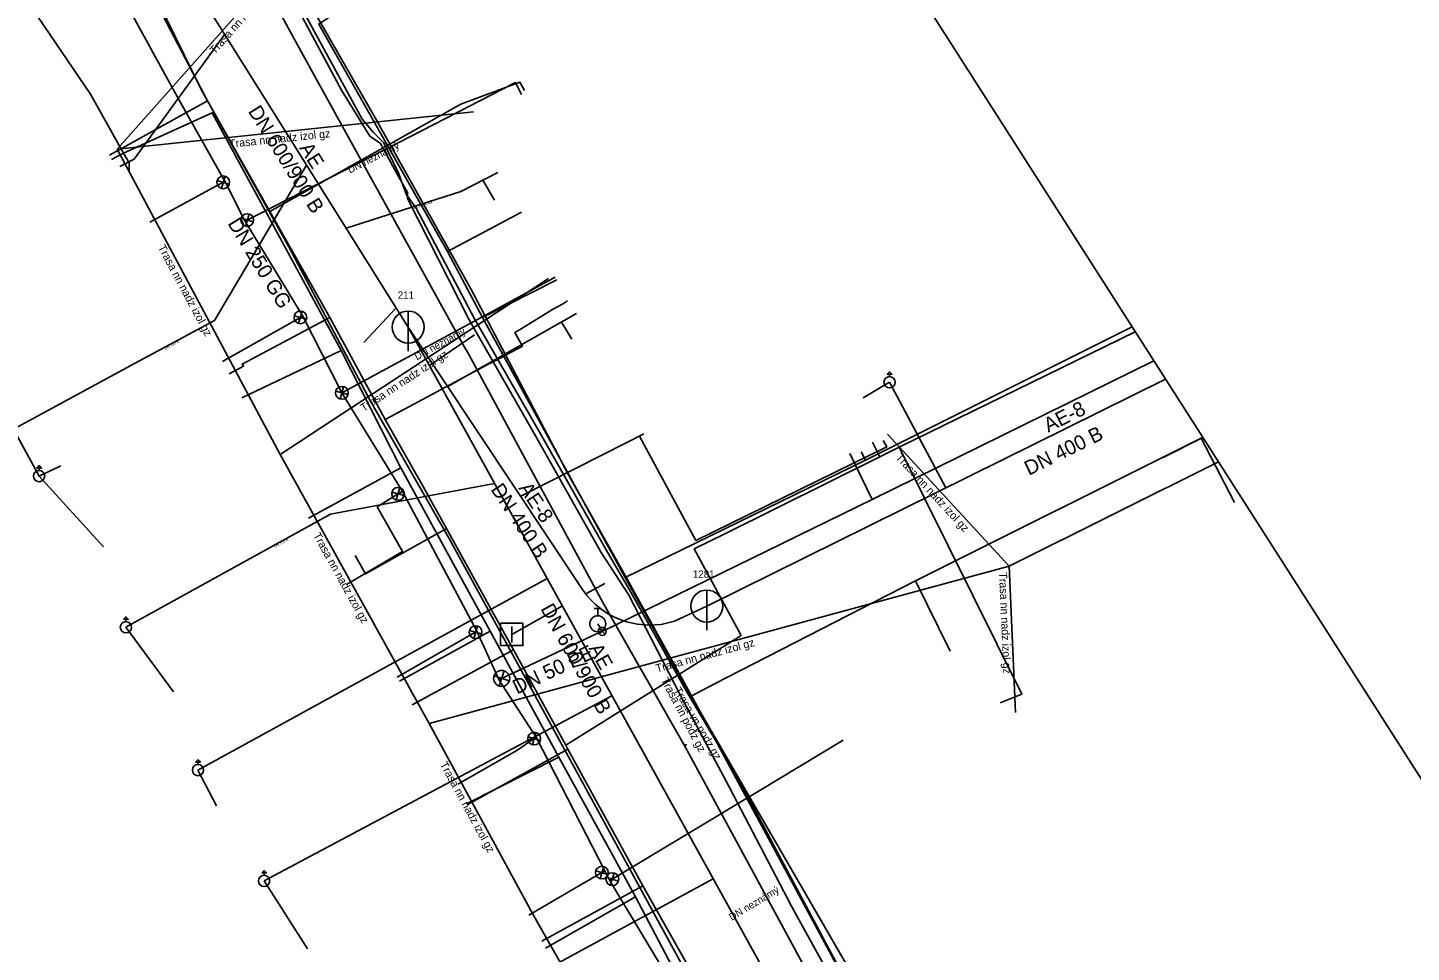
# Model space of a CAD drawing. Extents: x -493753 to -49291, y -1127285 to -112662.
# Drawn here: x -492942.9 to -492856.4, y -1126694.5 to -1126636.7 of the extents above; entities that cross this region are included whole.
import ezdxf

# ---------------------------------------------------------------- set-up
doc = ezdxf.new("R2010")
doc.units = 0
for name, color, linetype in [('Vrstva 1', 7, 'Continuous'), ('Vrstva 11', 7, 'Continuous'), ('Vrstva 15', 7, 'Continuous'), ('Vrstva 17', 7, 'Continuous'), ('Vrstva 19', 7, 'Continuous'), ('Vrstva 20', 7, 'Continuous'), ('Vrstva 22', 7, 'Continuous'), ('Vrstva 24', 7, 'Continuous'), ('Vrstva 26', 7, 'Continuous'), ('Vrstva 39', 7, 'Continuous'), ('Vrstva 5', 7, 'Continuous'), ('Vrstva 6', 7, 'Continuous'), ('Vrstva 9', 7, 'Continuous')]:
    doc.layers.add(name, color=color, linetype=linetype)

# ---------------------------------------------------------------- blocks, each defined once
blk = doc.blocks.new('_UZAVE')
at = {"layer": 'Vrstva 1'}
for p, q in [((-0.035, -0.035), (0.035, 0.035)), ((0.035, -0.035), (-0.035, 0.035))]:
    blk.add_line(p, q, dxfattribs=at)
for radius in [0.05, 0.0025]:
    blk.add_circle((0, 0), radius, dxfattribs=at)
blk = doc.blocks.new('_UZAV0')
at = {"layer": 'Vrstva 1'}
for p, q in [((-0.035, -0.035), (0.035, 0.035)), ((0.035, -0.035), (-0.035, 0.035))]:
    blk.add_line(p, q, dxfattribs=at)
for radius in [0.05, 0.0025]:
    blk.add_circle((0, 0), radius, dxfattribs=at)
blk = doc.blocks.new('_HYDRA')
at = {"layer": 'Vrstva 1'}
for p, q in [((-0.0225, 0.095), (0.0225, 0.095)), ((0, 0.095), (0, 0.05))]:
    blk.add_line(p, q, dxfattribs=at)
blk.add_circle((0, 0), 0.05, dxfattribs=at)
blk = doc.blocks.new('_VPUST')
at = {"layer": 'Vrstva 1'}
blk.add_line((0, 0.025), (0, -0.025), dxfattribs=at)
blk.add_lwpolyline([(-0.035, 0.035), (0.035, 0.035), (0.035, -0.035), (-0.035, -0.035), (-0.035, 0.035)], dxfattribs=at)
blk = doc.blocks.new('_SACHT')
at = {"layer": 'Vrstva 1'}
blk.add_line((0, 0.035), (0, 0.05), dxfattribs=at)
blk.add_lwpolyline([(-0.015, 0.05), (0, 0.065), (0.015, 0.05), (0.0025, 0.05)], close=True, dxfattribs=at)
blk.add_circle((0, 0), 0.035, dxfattribs=at)
blk = doc.blocks.new('_SACH0')
at = {"layer": 'Vrstva 1'}
blk.add_line((0, 0.05), (0, -0.075), dxfattribs=at)
blk.add_circle((0, 0), 0.05, dxfattribs=at)

msp = doc.modelspace()

# ---------------------------------------------------------------- linework, layer by layer
at = {"layer": 'Vrstva 1'}
for p, q in [((-492937.76, -1126644.71), (-492931.64, -1126641.3)), ((-492923.99, -1126654.85), (-492928.84, -1126657.42)), ((-492920.54, -1126661.22), (-492920.18, -1126661.03)), ((-492889.65, -1126663.54), (-492890.09, -1126662.64)), ((-492912.53, -1126675.61), (-492918.85, -1126679.05)), ((-492909.12, -1126681.82), (-492915.42, -1126685.29)), ((-492904.44, -1126690.35), (-492910.75, -1126693.81))]:
    msp.add_line(p, q, dxfattribs=at)
for points in [[(-493753.129, -1126773.634), (-493540.881, -1127284.865), (-492737.61, -1126868.64), (-492950.39, -1126535.73)], [(-492933.75, -1126611.37), (-492936.63, -1126613.76), (-492929.27, -1126628.23), (-492921.07, -1126642.52), (-492915.19, -1126653.05), (-492909.09, -1126664.67), (-492905.55, -1126670.97), (-492900.94, -1126679.32), (-492893.67, -1126692.81), (-492886.7, -1126705.75), (-492883.36, -1126711.37), (-492882.78, -1126712.34), (-492882.15, -1126713.4)], [(-492937.42, -1126630.24), (-492931.64, -1126641.3), (-492927.73, -1126648.23), (-492923.99, -1126654.85), (-492920.54, -1126661.22), (-492918.14, -1126665.44), (-492916.71, -1126668.03), (-492912.53, -1126675.61), (-492909.26, -1126681.56), (-492909.12, -1126681.82), (-492904.44, -1126690.35), (-492900.54, -1126697.23), (-492897.51, -1126702.99), (-492895.26, -1126707.27), (-492890.45, -1126716.07), (-492886.81, -1126722.78), (-492884.43, -1126727.16), (-492878.44, -1126738.04), (-492875.73, -1126742.95)], [(-492927.73, -1126648.23), (-492915.82, -1126641.52), (-492912.12, -1126640.14), (-492911.83, -1126640.66)], [(-492920.18, -1126661.03), (-492914.24, -1126657.85), (-492913.71, -1126657.58), (-492913, -1126657.2), (-492912.83, -1126657.1), (-492912.07, -1126656.7), (-492911.95, -1126656.63), (-492912.43, -1126655.78), (-492912.04, -1126655.55), (-492910.08, -1126654.34), (-492909.39, -1126653.97), (-492909.15, -1126653.81)], [(-492909.26, -1126681.56), (-492898.3, -1126674.7), (-492901.23, -1126669.3), (-492899.33, -1126668.35), (-492889.65, -1126663.54), (-492888.44, -1126662.95), (-492873.692, -1126655.73)], [(-492928.84, -1126657.42), (-492929.47, -1126657.75), (-492929.39, -1126657.89), (-492930.28, -1126658.36)], [(-492882.13, -1126678.91), (-492880.78, -1126678.38), (-492888.44, -1126662.95)], [(-492917.41, -1126668.42), (-492921.77, -1126670.86), (-492922.41, -1126669.72)], [(-492917.41, -1126668.42), (-492916.73, -1126668.04), (-492916.71, -1126668.03)]]:
    msp.add_lwpolyline(points, dxfattribs=at)
at = {"layer": 'Vrstva 11'}
msp.add_lwpolyline([(-492848.73, -1126797.53), (-492854.56, -1126788.15), (-492854.38, -1126786.02), (-492853.2, -1126784.39), (-492859.9, -1126772.1), (-492871.87, -1126750.4), (-492886.74, -1126723.34), (-492898.4, -1126701.86), (-492908, -1126684.26), (-492916.54, -1126668.65), (-492921.45, -1126660.08), (-492926.55, -1126650.44), (-492932.03, -1126640.6), (-492935.8, -1126632.89)], dxfattribs=at)
at = {"layer": 'Vrstva 15'}
for p, q in [((-492919.1, -1126655.44), (-492931.9, -1126635.01)), ((-492913.71, -1126647.52), (-492914.44, -1126646.27)), ((-492921.87, -1126656.41), (-492919.84, -1126654.25)), ((-492908.58, -1126654.6), (-492916.63, -1126659.16)), ((-492895.82, -1126697.55), (-492919.1, -1126655.44)), ((-492908.87, -1126656.2), (-492909.52, -1126655.13)), ((-492914.96, -1126655.92), (-492917.77, -1126657.84)), ((-492871.793, -1126658.701), (-492900.45, -1126672.87)), ((-492890.69, -1126659.87), (-492889.03, -1126658.89)), ((-492889.03, -1126658.89), (-492885.52, -1126665.49)), ((-492942.15, -1126664.75), (-492943.76, -1126661.81)), ((-492904.39, -1126662.11), (-492905.39, -1126662.63)), ((-492905.39, -1126662.63), (-492912.07, -1126666.01)), ((-492940.8, -1126664.11), (-492942.15, -1126664.75)), ((-492938.12, -1126669.18), (-492942.15, -1126664.75)), ((-492932.23, -1126683.12), (-492910.41, -1126671.15)), ((-492906.82, -1126671.47), (-492908.01, -1126672.1)), ((-492912.63, -1126674.64), (-492909.47, -1126672.85)), ((-492936.73, -1126674.19), (-492936.73, -1126674.19)), ((-492933.76, -1126678.23), (-492936.73, -1126674.19)), ((-492928.1, -1126690.04), (-492906.37, -1126678.47)), ((-492931.07, -1126685.36), (-492932.23, -1126683.12)), ((-492925.38, -1126694.29), (-492928.1, -1126690.04)), ((-492922.12, -1126701.88), (-492900.04, -1126689.91))]:
    msp.add_line(p, q, dxfattribs=at)
for points in [[(-492937.11, -1126645.41), (-492936.22, -1126644.95), (-492930.56, -1126637.15)], [(-492943.76, -1126661.81), (-492936.19, -1126657.72), (-492931.2, -1126655.03), (-492925.44, -1126645.32)], [(-492913.49, -1126645.79), (-492915.82, -1126646.97), (-492922.97, -1126649.26)], [(-492900.45, -1126672.87), (-492902.46, -1126673.82), (-492903.29, -1126674.02), (-492904.07, -1126674.07), (-492904.78, -1126674.01), (-492905.47, -1126673.86), (-492906.02, -1126673.65), (-492906.52, -1126673.41), (-492907.06, -1126673.05), (-492907.4, -1126672.77), (-492907.63, -1126672.54), (-492907.93, -1126672.21), (-492908.21, -1126671.83), (-492919.1, -1126655.44)], [(-492889.43, -1126662.52), (-492889.21, -1126662.93), (-492901.14, -1126668.77), (-492904.66, -1126662.25)], [(-492936.73, -1126674.19), (-492923.95, -1126667.14), (-492913.7, -1126665.21)]]:
    msp.add_lwpolyline(points, dxfattribs=at)
at = {"layer": 'Vrstva 20'}
for p, q in [((-492935.23, -1126648.88), (-492931.72, -1126646.98)), ((-492909.91, -1126652.33), (-492913.55, -1126654.3)), ((-492913.55, -1126654.3), (-492923.24, -1126659.55)), ((-492930.69, -1126657.59), (-492927.02, -1126655.51)), ((-492891.52, -1126663.35), (-492890.11, -1126666.22)), ((-492906.98, -1126674.45), (-492907.26, -1126673.98)), ((-492916.1, -1126675.19), (-492919.79, -1126677.31)), ((-492891.93, -1126681.25), (-492897.29, -1126684.47)), ((-492915.99, -1126684), (-492912.32, -1126681.89)), ((-492908.14, -1126690.19), (-492907.97, -1126690.08)), ((-492911.57, -1126692.18), (-492908.14, -1126690.19))]:
    msp.add_line(p, q, dxfattribs=at)
for points in [[(-492913.41, -1126677.49), (-492914.81, -1126674.43), (-492919.46, -1126665.71), (-492923.24, -1126659.55), (-492925.68, -1126654.76), (-492929.3, -1126648.81), (-492930.54, -1126646.38), (-492933.4, -1126641.26), (-492941.69, -1126626.18)], [(-492912.02, -1126640.91), (-492912.39, -1126640.17), (-492919.72, -1126643.93)], [(-492919.72, -1126643.93), (-492929.15, -1126648.76), (-492929.3, -1126648.81)], [(-492931.72, -1126646.98), (-492930.65, -1126646.4), (-492930.54, -1126646.38)], [(-492927.02, -1126655.51), (-492925.83, -1126654.84), (-492925.68, -1126654.76)], [(-492907.33, -1126674.6), (-492906.98, -1126674.45), (-492890.11, -1126666.22), (-492872.529, -1126657.55)], [(-492921.03, -1126666.67), (-492919.73, -1126665.86), (-492919.46, -1126665.71)], [(-492921.03, -1126666.67), (-492919.46, -1126669.47), (-492922.96, -1126671.52)], [(-492914.81, -1126674.43), (-492914.89, -1126674.5), (-492916.1, -1126675.19)], [(-492913.41, -1126677.49), (-492913.26, -1126677.39), (-492907.33, -1126674.6)], [(-492852.32, -1126789.23), (-492857.95, -1126778.05), (-492862.82, -1126769.39), (-492866.35, -1126762.51), (-492876.86, -1126743.48), (-492879.77, -1126737.71), (-492881.46, -1126734.83), (-492885.64, -1126727.14), (-492890.48, -1126718.68), (-492890.54, -1126718.22), (-492897.26, -1126705.96), (-492901.5, -1126698.34), (-492906.52, -1126690), (-492906.82, -1126689.41), (-492911.08, -1126681.1), (-492913.41, -1126677.49)], [(-492912.32, -1126681.89), (-492911.23, -1126681.15), (-492911.08, -1126681.1)], [(-492897.29, -1126684.47), (-492906.35, -1126689.93), (-492906.52, -1126690)], [(-492907.97, -1126690.08), (-492907, -1126689.52), (-492906.82, -1126689.41)]]:
    msp.add_lwpolyline(points, dxfattribs=at)
at = {"layer": 'Vrstva 26'}
for p, q in [((-492924.85, -1126639.93), (-492930.84, -1126629)), ((-492915.47, -1126656.88), (-492924.85, -1126639.93)), ((-492915.47, -1126656.88), (-492915.45, -1126656.89)), ((-492906.94, -1126672.65), (-492915.45, -1126656.89)), ((-492869.466, -1126662.341), (-492871.95, -1126663.6)), ((-492901.81, -1126681.63), (-492906.94, -1126672.65)), ((-492901.72, -1126681.49), (-492901.81, -1126681.63)), ((-492889.99, -1126703.43), (-492901.81, -1126681.63))]:
    msp.add_line(p, q, dxfattribs=at)
at = {"layer": 'Vrstva 39'}
for points in [[(-492936.87, -1126644.57), (-492938.94, -1126640.9), (-492942.91, -1126635.05), (-492945.91, -1126631.38), (-492948.69, -1126626.8), (-492951.91, -1126622.62), (-492954.47, -1126619.53), (-492955.78, -1126619.9)], [(-492916.64, -1126650.73), (-492924.68, -1126636.52), (-492920.28, -1126633.53)], [(-492936.87, -1126644.57), (-492931.34, -1126642.05), (-492923.28, -1126656.91)], [(-492936.87, -1126644.57), (-492937.62, -1126644.97)], [(-492936.53, -1126645.64), (-492936.53, -1126645.18), (-492936.87, -1126644.57)], [(-492916.64, -1126650.73), (-492912.02, -1126648.26)], [(-492914.46, -1126654.84), (-492916.64, -1126650.73)], [(-492914.46, -1126654.84), (-492909.82, -1126652.5)], [(-492914.46, -1126654.84), (-492905.55, -1126671.08)], [(-492890.54, -1126663.76), (-492875.66, -1126656.32), (-492873.882, -1126655.432)], [(-492923.28, -1126656.91), (-492929.48, -1126659.87)], [(-492919.56, -1126664.24), (-492923.28, -1126656.91)], [(-492869.56, -1126662.38), (-492887.42, -1126671.29)], [(-492869.56, -1126662.38), (-492869.47, -1126662.335)], [(-492869.56, -1126662.38), (-492867.48, -1126666.4)], [(-492890.54, -1126663.76), (-492890.81, -1126663.23)], [(-492890.54, -1126663.76), (-492905.55, -1126671.08)], [(-492919.56, -1126664.24), (-492925.33, -1126667.38)], [(-492919.56, -1126664.24), (-492917.02, -1126668.88)], [(-492917.02, -1126668.88), (-492913.98, -1126674.44)], [(-492901.42, -1126678.49), (-492905.55, -1126671.08)], [(-492899.96, -1126677.73), (-492887.42, -1126671.29)], [(-492887.42, -1126671.29), (-492885.24, -1126675.68)], [(-492913.98, -1126674.44), (-492919.65, -1126677.57)], [(-492913.98, -1126674.44), (-492909.69, -1126682.31)], [(-492901.42, -1126678.49), (-492899.96, -1126677.73)], [(-492901.42, -1126678.49), (-492890.35, -1126697.64)], [(-492909.69, -1126682.31), (-492915.46, -1126685.23)], [(-492909.69, -1126682.31), (-492904.9, -1126691.03)], [(-492904.9, -1126691.03), (-492910.52, -1126694.24)], [(-492904.9, -1126691.03), (-492901.8, -1126696.93)]]:
    msp.add_lwpolyline(points, dxfattribs=at)
at = {"layer": 'Vrstva 5'}
for points in [[(-492937.28, -1126644.33), (-492920.46, -1126625.39)], [(-492930.18, -1126627.53), (-492929.7, -1126628.3), (-492927.22, -1126633.26), (-492923.26, -1126640.65), (-492921.49, -1126643.52), (-492920.82, -1126643.97), (-492919.81, -1126645.85), (-492919.15, -1126647.03), (-492919.14, -1126647.42), (-492915.28, -1126654.98), (-492910.97, -1126662.52), (-492907.05, -1126669.53), (-492905.34, -1126672.14), (-492902.08, -1126678.46), (-492899.06, -1126684.17), (-492895.14, -1126691.66), (-492891.32, -1126698.58), (-492884.38, -1126711.3), (-492880.56, -1126717.84), (-492878.06, -1126722.71), (-492874.49, -1126729.25), (-492872.37, -1126733.14)], [(-492915.01, -1126641.99), (-492937.28, -1126644.33)], [(-492937.28, -1126644.33), (-492927.1, -1126663.41)], [(-492910.34, -1126652.4), (-492927.1, -1126663.41)], [(-492881.56, -1126670.38), (-492889.16, -1126662.14)], [(-492927.1, -1126663.41), (-492917.78, -1126680.21)], [(-492868.492, -1126663.866), (-492881.56, -1126670.38)], [(-492881.56, -1126670.38), (-492917.78, -1126680.21)], [(-492881.56, -1126670.38), (-492881.17, -1126679.51)], [(-492917.78, -1126680.21), (-492911.33, -1126692.08)], [(-492911.33, -1126692.08), (-492904.3, -1126704.49)]]:
    msp.add_lwpolyline(points, dxfattribs=at)
at = {"layer": 'Vrstva 6'}
msp.add_lwpolyline([(-492927.01, -1126633.18), (-492921.98, -1126642.45), (-492921.27, -1126643.29), (-492920.62, -1126643.94), (-492919.69, -1126645.86), (-492919.21, -1126647.18), (-492918.59, -1126648.02), (-492914.95, -1126654.92), (-492910.66, -1126662.41), (-492906.73, -1126669.35), (-492905.2, -1126672), (-492901.68, -1126678.27), (-492898.39, -1126683.83), (-492894.4, -1126691.31), (-492890.71, -1126698.27), (-492886.43, -1126705.66), (-492883.76, -1126710.99), (-492880.09, -1126717.64), (-492877.39, -1126722.45), (-492873.92, -1126729.01), (-492870.04, -1126736.47), (-492865.33, -1126745.11)], dxfattribs=at)

# ---------------------------------------------------------------- block references
at = {"layer": 'Vrstva 17'}
for name, p, xscale, yscale in [('_SACH0', (-492919.1, -1126655.44), 19.997500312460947, 19.997500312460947), ('_SACHT', (-492889.03, -1126658.89), 9.998750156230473, 9.998750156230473), ('_SACHT', (-492942.15, -1126664.75), 9.998750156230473, 9.998750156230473), ('_SACH0', (-492900.45, -1126672.87), 19.997500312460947, 19.997500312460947), ('_SACHT', (-492936.73, -1126674.19), 9.998750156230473, 9.998750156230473), ('_VPUST', (-492912.63, -1126674.64), 19.997500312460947, 19.997500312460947), ('_SACHT', (-492932.23, -1126683.12), 9.998750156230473, 9.998750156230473), ('_SACHT', (-492928.1, -1126690.04), 9.998750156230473, 9.998750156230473)]:
    msp.add_blockref(name, p, dxfattribs=dict(at, xscale=xscale, yscale=yscale))
at = {"layer": 'Vrstva 22'}
for name, p, xscale, yscale, rotation in [('_UZAV0', (-492930.65, -1126646.4), 7.999000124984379, 7.999000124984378, 28.054280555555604), ('_UZAV0', (-492929.15, -1126648.76), 7.999000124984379, 7.999000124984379, -62.433819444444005), ('_UZAV0', (-492925.83, -1126654.84), 7.999000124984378, 7.999000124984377, -61.06460277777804), ('_UZAV0', (-492923.24, -1126659.55), 7.999000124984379, 7.999000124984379, -60.13995555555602), ('_UZAV0', (-492919.73, -1126665.86), 7.999000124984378, 7.999000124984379, 118.49356111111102), ('_UZAV0', (-492914.89, -1126674.5), 7.99900012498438, 7.99900012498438, 118.52230277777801), ('_UZAVE', (-492913.26, -1126677.39), 9.998750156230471, 9.998750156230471, 26.326419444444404), ('_UZAV0', (-492911.23, -1126681.15), 7.999000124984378, 7.999000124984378, 118.278711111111), ('_UZAV0', (-492907, -1126689.52), 7.999000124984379, 7.999000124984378, -61.50281944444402), ('_UZAV0', (-492906.35, -1126689.93), 7.99900012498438, 7.999000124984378, 116.95641111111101)]:
    msp.add_blockref(name, p, dxfattribs=dict(at, xscale=xscale, yscale=yscale, rotation=rotation))
for name, p, xscale, yscale in [('_HYDRA', (-492907.26, -1126673.98), 9.998750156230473, 9.998750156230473), ('_UZAVE', (-492906.98, -1126674.45), 4.999375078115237, 4.999375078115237)]:
    msp.add_blockref(name, p, dxfattribs=dict(at, xscale=xscale, yscale=yscale))

# ---------------------------------------------------------------- texts
at = {"layer": 'Vrstva 19'}
for s, height, rotation, p in [('DN 600/900 B', 0.90989, 302.07567, (-492929.128, -1126641.958)), ('AE', 0.9099, 302.07567, (-492925.926, -1126644.259)), ('DN 200 KAM', 0.1605, 17.75276, (-492918.806, -1126648.098)), ('DN 150 B', 0.1605, 28.39944, (-492934.252, -1126656.856)), ('AE-8', 0.9099, 26.30967, (-492879.123, -1126662.044)), ('DN 400 B', 0.9099, 26.30967, (-492880.332, -1126664.736)), ('DN 400 B', 0.9099, 303.58993, (-492913.976, -1126665.585)), ('AE-8', 0.9099, 303.58993, (-492912.226, -1126665.506)), ('DN 150 B', 0.1605, 28.86725, (-492927.409, -1126669.229)), ('DN 600/900 B', 0.90989, 298.9326, (-492910.857, -1126673.03)), ('AE', 0.9099, 298.9326, (-492907.85, -1126675.508))]:
    msp.add_text(s, height=height, rotation=rotation, dxfattribs=at).set_placement(p)
for s, p in [('211', (-492919.752, -1126653.67)), ('1281', (-492901.316, -1126671.1))]:
    msp.add_text(s, height=0.4549, dxfattribs=at).set_placement(p)
at = {"layer": 'Vrstva 24'}
for s, height, rotation, p in [('DN neznámý', 0.455, 27.1365, (-492922.737, -1126645.856)), ('DN 250 GG', 0.9099, 301.31648, (-492930.403, -1126648.96)), ('DN neznámý', 0.455, 28.46328, (-492918.555, -1126657.525)), ('DN 50 PE', 0.9099, 25.23711, (-492912.309, -1126678.398)), ('DN neznámý', 0.455, 31.06159, (-492898.889, -1126692.538))]:
    msp.add_text(s, height=height, rotation=rotation, dxfattribs=at).set_placement(p)
at = {"layer": 'Vrstva 9'}
for s, rotation, p in [('Trasa nn nadz izol gz', 48.3975, (-492931.177, -1126638.433)), ('Trasa nn nadz izol gz', 6.00174, (-492930.259, -1126644.246)), ('Trasa nn nadz izol gz', 298.07498, (-492934.745, -1126650.461)), ('Trasa nn nadz izol gz', 33.30156, (-492921.879, -1126660.753)), ('Trasa nn nadz izol gz', 312.68339, (-492888.685, -1126663.614)), ('Trasa nn nadz izol gz', 299.02709, (-492925.052, -1126668.447)), ('Trasa nn nadz izol gz', 272.46197, (-492882.195, -1126670.767)), ('Trasa nn nadz izol gz', 15.18519, (-492903.56, -1126677.022)), ('Trasa nn podz gz', 297.90926, (-492903.329, -1126677.49)), ('Trasa vn podz gz', 300.64304, (-492902.531, -1126678.12)), ('Trasa nn nadz izol gz', 298.52051, (-492917.132, -1126682.757))]:
    msp.add_text(s, height=0.5, rotation=rotation, dxfattribs=at).set_placement(p)

doc.saveas('drawing.dxf')
